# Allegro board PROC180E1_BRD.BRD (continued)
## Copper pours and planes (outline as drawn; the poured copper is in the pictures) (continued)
DGND on TOP: 117.58,45.41 116.52,45.41 116.52,43.52 117.58,43.52
DGND on TOP: 128.6,47.74 129.79,47.74 129.79,49.33 128.6,49.33
DGND on TOP: 53.99,21.67 53.99,17.76 56.74,17.76 56.74,21.67
DGND on TOP: 21.53,36.95 21.53,35.67 22.63,35.67 22.63,36.95
DGND on TOP: 130.52,130.5 130.5,130.52 128.37,130.52 127.78,131.11 127.78,137.09 128.48,137.8 133.89,137.8 134.19,137.51 134.19,130.85 133.84,130.5
DGND on TOP: 129.33,45.57 125.72,45.57 125.72,43.91 128.69,43.91 129.33,44.55
DGND on TOP: 85.16,45.41 84.09,45.41 84.09,43.52 85.16,43.52
DGND on TOP: 116.73,66.74 116.73,65.64 118.02,65.64 118.02,66.74
DGND on TOP: 125.58,45.41 124.52,45.41 124.52,43.52 125.58,43.52
DGND on TOP: 14.65,145.07 14.65,141.22 14.6,141.17 13.11,141.17 12.99,141.3 12.99,145 13.06,145.07
DGND on TOP: 63.89,24.66 63.89,26.79 63.65,27.03 62.17,27.03 62.06,26.93 62.06,22.52 63.07,22.52 63.07,24.25 63.31,24.5 63.73,24.5
DGND on TOP: 13.99,1.02 11.02,3.99 11.02,19.74 15.52,19.74 15.52,11.07 16.32,10.27 16.32,8.75 17.99,7.08 25.49,7.08 25.49,1.02
DGND on TOP: 43.11,57.6 43.24,57.47 43.24,56.31 43.42,56.13 46.29,56.13 46.7,56.54 47.08,56.54 47.48,56.13 50.15,56.13 50.58,56.57 50.58,57.05 51.11,57.58 53.62,57.58 55,56.2 55,55.04 54.87,54.91 54.49,54.91 54.32,55.09 39.74,55.09 39.43,54.79 38.77,54.79 38.62,54.94 38.62,56.54 39.68,57.6
DGND on TOP: 53.83,69.04 54.04,68.83 54.04,67.03 53.73,66.73 50.58,66.73 50.51,66.8 50.51,68.35 50.4,68.45 47.38,68.45 47.05,68.12 46.67,68.12 46.34,68.45 43.52,68.45 43.16,68.1 43.16,66.6 42.99,66.42 39.71,66.42 39.46,66.67 39.46,68.88 39.61,69.04
DGND on TOP: 12.9,157.48 12.9,155.14 14.61,155.14 14.61,157.48
DGND on BOTTOM: 51.81,11.24 51.81,9.41 53.77,9.41 53.77,11.24
DGND on BOTTOM: 84.4,114.79 83.74,114.79 83.67,114.72 83.67,113.24 83.5,113.06 83.5,112.58 83.56,112.52 84.31,112.52 84.53,112.74 84.53,112.74 84.53,114.65
DGND on BOTTOM: 130.31,43.61 131.75,43.61 131.75,47.23 131.58,47.41 130.01,47.41 129.74,47.14 129.74,44.18
DGND on BOTTOM: 48.81,19.31 47.46,19.31 47.22,19.07 47.22,16.83 47.38,16.68 48.75,16.68 49.03,16.96 49.03,19.08
DGND on BOTTOM: 54.1,11.7 54.1,8.87 57.43,8.87 57.43,11.7
DGND on BOTTOM: 31.62,10.24 31.62,12.77 27.95,12.77 27,11.82 27,10.01 27.18,9.83 31.2,9.83
DGND on BOTTOM: 67.48,164.73 69.07,164.73 69.26,164.92 69.26,166.18 68.91,166.54 67.74,166.54 67.48,166.28
DGND on BOTTOM: 66.2,16.08 66.2,12.42 69.75,12.42 69.75,16.08
DGND on BOTTOM: 83.85,158.03 83.85,155.93 84.25,155.53 85.12,155.53 85.48,155.88 85.48,157.43 84.75,158.16 83.99,158.16
DGND on BOTTOM: 27.57,30.82 23.78,30.82 23.78,25.36 27.57,25.36
DGND on BOTTOM: 92.43,35.21 90.26,35.21 90.08,35.03 90.08,34.39 90.2,34.27 91.12,34.27 91.31,34.08 91.31,33.11 91.62,32.81 91.62,31.98 91.68,31.92 92.99,31.92 93.25,32.18 93.25,32.4 92.79,32.86 92.79,33.8 92.43,34.16
DGND on BOTTOM: 44.92,55.89 44.92,51.71 48.92,51.71 48.92,56.1 49.02,56.21 53.7,56.21 53.79,56.3 53.79,57.83 53.69,57.94 44.33,57.94 44.1,58.17 44.1,61.14 44.76,61.8 45.93,61.8 46.29,61.44 46.26,61.42 46.26,60.6 46.37,60.5 47.46,60.5 47.61,60.66 47.61,61.65 47.84,61.87 49.11,61.87 49.31,61.67 49.31,61.47 49.36,61.42 49.84,61.42 50,61.57 50,62.51 49.77,62.74 47.61,62.74 47.48,62.87 47.51,62.89 47.51,63.86 47.3,64.06 46.29,64.06 46.14,63.91 46.14,62.89 45.83,62.59 41.84,62.59 41.64,62.79 41.64,63.55 42.43,64.34 42.43,67.89 41.49,68.83 40.12,68.83 39.71,68.43 39.71,56.42 40.08,56.05 44.76,56.05
DGND on BOTTOM: 93.38,30.45 93.38,27.61 95.02,27.61 95.02,30.45
DGND on BOTTOM: 69.8,114.93 68.5,114.93 68.37,114.8 68.37,114.13 68.47,114.02 69.74,114.02 69.85,114.14 69.85,114.88
DGND on BOTTOM: 82.05,75.1 84.43,75.1 89.05,70.48 89.05,53.33 84.2,48.47 63.79,48.47 61.25,51.01 61.25,69.91 64.79,73.45 68.48,73.45 68.76,73.17 68.76,72.47 64.13,67.84 64.13,51.49 66.01,49.61 69.62,49.61 69.92,49.9 69.92,50.63 70.29,51 84.01,51 85.11,52.11 85.11,69.03 84.05,70.09 84.05,70.82 84.13,70.9 84.13,71.42 83.53,72.03 83.53,72.57 82.2,73.89 82.17,73.89 82.05,74.01
DGND on BOTTOM: 42.96,66.32 53.07,66.32 53.58,66.83 53.58,68.86 53.45,68.99 51.92,68.99 51.79,68.86 41.9,68.86 41.52,69.24 40.44,69.24 40.2,69 40.2,64.81 40.7,64.31 42.3,64.31 42.43,64.44 42.43,65.79
DGND on BOTTOM: 66.55,114.9 65.41,114.9 65.41,114.66 65.41,114.66 65.41,114.1 65.1,113.79 65.1,113.16 65.2,113.06 65.53,113.06 65.91,113.45 65.91,113.75 66.55,114.39
DGND on BOTTOM: 53.43,30.1 53.43,26.46 56.27,26.46 56.27,30.1
DGND on BOTTOM: 53.38,22.97 53.38,18.57 56.86,18.57 56.86,22.97
DGND on L02_GND01: 11.02,4.99 11.02,184.36 13.47,186.82 134.49,186.82 135.98,185.32 135.98,6.56 132.29,6.56 130.45,4.72 130.45,1.02 14.99,1.02 ; 2 cut-outs
DGND on L04_PWR1: 85.11,111.33 85.11,98.21 91.68,91.63 91.68,79.61 91.33,79.27 90.6,79.27 89.86,78.53 89.86,59.49 82.54,52.17 71.02,52.17 70.34,51.49 70.34,41.43 71.08,40.69 73.18,40.69 79.59,34.28 93.41,34.28 95.12,35.99 120.9,35.99 121.78,36.88 121.78,56.74 114.57,63.95 110.66,63.95 105.75,68.87 105.75,95.24 104.2,96.79 104.2,108.88 96.42,116.66 92.2,116.66 89.23,119.64 89.23,123.92 90.75,125.44 93.19,125.44 93.6,125.85 93.6,126.66 93.24,127.02 85.04,127.02 84.35,126.33 84.35,115.67 83.75,115.07 83.75,112.68
DGND on L04_PWR1: 73.28,14.15 134.94,14.15 135.91,13.18 135.91,5.95 131.12,1.16 73.28,1.16
DGND on L05_SIG02: 59.79,70.16 60.58,70.16 61.57,69.17 61.57,59.86 66.53,54.9 82.35,54.9 86.8,59.35 86.8,69.11 81.9,74.01 81.9,76.97 83.06,78.13 86.37,78.13 90.89,73.61 90.89,54.67 85.84,49.62 64.08,49.62 58.04,55.66 58.04,68.41
DGND on L05_SIG02: 73.51,12.63 73.51,1.18 131.27,1.18 135.82,5.74 135.82,18.55 69.97,18.55 67.57,20.96 67.57,25.18 66.56,26.19 64.01,26.19 63.37,25.55 63.37,22.56 61.55,20.75 61.55,13.33 72.81,13.33
DGND on L05_SIG02: 17.93,38.39 20.06,38.39 20.7,37.75 20.7,32.45 22.25,30.9 22.25,20.12 25.72,16.66 25.72,1.92 25.27,1.48 15.05,1.48 11.13,5.41 11.13,23.97 11.29,24.14 14.74,24.14 17.25,26.64 17.25,37.71
DGND on L06_PWR2: 61.58,59.46 66.23,54.81 82.26,54.81 86.49,59.05 86.49,71.03 81.3,76.22 75.98,76.22 74.64,74.87 69.15,74.87 68.44,75.58 67.4,75.58 67.22,75.4 67.22,75.2 66.84,74.81 65.09,74.81 64.38,74.11 64.38,73.77 61.58,70.98
DGND on L07_GND02: 11.02,4.99 11.02,184.36 13.47,186.82 134.49,186.82 135.98,185.32 135.98,6.56 132.29,6.56 130.45,4.72 130.45,1.02 14.99,1.02 ; 7 cut-outs
DVDD3V3 on TOP: 51.57,62.43 52.26,62.43 52.46,62.23 52.46,61.09 52.31,60.93 51.22,60.93 50.94,61.21 50.94,61.47 51.34,61.87 51.34,62.2
VBAT_IN on TOP: 79.48,169.52 79.48,166.92 80.92,165.49 80.92,164.25 81.01,164.16 81.21,163.96 81.21,162.62 81.43,162.62 81.45,162.64 81.45,164.11 81.4,164.15 81.4,164.99 81.54,165.13 81.54,169.41 81.43,169.52
VBUS_5V0_TYPEA on TOP: 60.63,12.42 60.63,11.57 60.87,11.33 62.18,11.33 62.33,11.48 62.33,15.29 62.32,15.29 63.22,16.19 63.22,19.77 62.94,20.04 59.87,20.04 59.87,13.18
VBUS_5V0_TYPEA on BOTTOM: 67.43,20.45 61.13,20.45 60.85,20.17 60.85,17.64 65.2,17.64 65.2,16.98 66.2,16.98 66.2,17.95 67.42,17.95 67.62,18.15 67.62,20.26
VBUS_5V0_TYPEA on BOTTOM: 60.6,15.13 60.6,11.36 64.06,11.36 64.06,15.13
VBUS_TYPEC1 on L05_SIG02 (solid shape): outline of 1023 points within 26.3,4.67 37.85,18.54
VBUS_TYPEC2 on BOTTOM (solid shape): outline of 424 points within 42.91,5.2 58.47,17.56
VBUS_TYPEC2 on L05_SIG02: 41.25,11.08 41.25,22.44 46.35,22.44 48.3,20.48 48.3,17.54 48.97,16.87 58.99,16.87 59.23,16.64 59.23,13.49 58.26,12.53 54.23,12.53 52.15,10.45 52.15,5.34 51.54,4.74 46.84,4.74 46.44,5.14 46.44,8.84 44.19,11.08
VCC1V1 on TOP: 55.01,54.55 47.42,54.55 47.42,51.18 56.82,51.18 56.82,53.54 55.5,53.54 55.01,54.03
VCC1V1 on BOTTOM: 49.54,55.85 49.54,51.66 54.01,51.66 54.01,55.85
VCC1V1_SW on TOP: 50.2,56.46 50.2,57.98 50.03,58.16 48.84,58.16 47.54,59.46 47.54,60.62 47.21,60.62 47.21,56.46
VCC1V8_SYS on TOP: 14.42,105.56 18.4,105.56 18.52,105.45 18.52,104.19 18.44,104.11 16,104.11 15.77,104.34 14.47,104.34 14.41,104.4 14.41,105.55
VCC1V8_SYS on TOP: 132.58,131.95 128.6,131.95 128.48,132.06 128.48,133.32 128.56,133.4 131,133.4 131.23,133.17 132.53,133.17 132.59,133.11 132.59,131.96
VCC1V8_SYS on TOP: 46.14,54.51 46.14,49.89 38.43,49.89 37.63,50.69 37.63,54.17 37.96,54.51
VCC1V8_SYS on TOP: 87.55,152.35 87.55,154.46 85,154.46 85,152.35
VCC1V8_SYS on TOP: 42.91,156.11 42.91,155.17 43.12,154.97 44.43,154.97 44.6,155.14 44.6,155.73 44.23,156.11
VCC1V8_SYS on TOP: 118.38,142.05 118.38,139.95 118.59,139.74 119.36,139.74 119.52,139.9 119.52,141.97 119.44,142.05
VCC1V8_SYS on TOP: 52.56,65.41 52.56,64.74 52.38,64.57 51.42,64.57 50.53,63.68 49.57,63.68 49.5,63.74 49.5,63.96 49.53,63.98 50.2,63.98 50.28,64.06 50.28,64.47 50.91,65.11 50.91,65.43 51.09,65.61 52.36,65.61
VCC1V8_SYS on BOTTOM: 44.18,51.92 44.18,55.48 39.87,55.48 38.61,54.22 37.68,54.22 37.68,50.72 42.99,50.72
VCC1V8_SYS on BOTTOM: 64.16,117.64 64.16,116.53 64.3,116.39 65.07,116.39 65.32,116.64 65.32,117.72 65.25,117.79 64.31,117.79
VCC1V8_SYS on BOTTOM: 104.11,73.73 105.75,73.73 105.77,73.71 105.77,72.57 105.53,72.33 104.31,72.33 104.08,72.56 104.08,73.69
VCC1V8_SYS on BOTTOM: 83.89,110.51 84.72,110.51 84.99,110.78 84.99,111.5 84.74,111.75 83.89,111.75 83.76,111.62 83.76,110.64
VCC1V8_SYS on L03_SIG01: 94,163.07 94,158.76 95.02,157.73 112.41,157.73 115.63,160.94 116.65,160.94 118.17,159.42 131.33,159.42 133.21,161.3 133.21,162.41 132.69,162.92 130.64,162.92 130.12,162.41 116.55,162.41 115.52,163.43 112.7,163.43 112.21,162.95 101.1,162.95 100.59,163.46 94.38,163.46 ; 2 cut-outs
VCC1V8_SYS on L04_PWR1: 52.15,65.8 47.8,65.8 47.29,65.3 45.75,65.3 44.61,64.15 44.61,60.98 43.16,59.54 41.31,59.54 40.35,58.58 31.99,58.58 30.96,57.55 28.01,57.55 25.95,55.49 25.95,42.36 27.1,41.22 29.58,41.22 34.68,46.31 34.68,49.42 35.89,50.63 49.26,50.63 50.2,51.56 50.2,61.99 50.62,62.41 52.34,62.41 52.59,62.66 52.59,65.36
VCC1V8_SYS on L05_SIG02: 59.97,38.71 36.21,38.71 20.42,54.49 20.42,96.99 23.54,100.11 23.54,108.2 25.35,110.01 41.21,110.01 41.56,109.67 41.56,95.18 37.14,90.76 37.14,59.54 40.29,56.38 40.29,51.32 39.7,50.73 39.7,47.22 40.44,46.49 65.34,46.49 67.3,44.53 67.3,29.09 65.79,27.58 64.76,27.58 59.97,32.37
VCC1V8_SYS on L06_PWR2: 11.99,85.48 14.59,82.88 27.37,82.88 32.84,88.34 61.43,88.34 65.28,92.18 92.17,92.18 94.49,89.86 94.49,79.55 91.72,76.78 91.72,67.74 94.11,65.35 94.38,65.35 95.97,63.76 95.97,62.8 97.35,61.42 104.85,61.42 105.07,61.64 105.07,103.95 109.99,108.87 118.31,108.87 118.31,117.82 114.47,121.66 109.86,121.66 109.36,122.16 109.36,126.95 112.43,130.02 133.92,130.02 135.1,131.19 135.1,184.48 132.9,186.68 14.01,186.68 11.99,184.66
VCC1V8_SYS_SW on TOP: 43.52,56.46 43.52,58.16 44.9,58.16 46.21,59.46 46.21,60.62 46.54,60.62 46.54,56.46
VCC1V8_VDD18 on L03_SIG01: 42.95,156.15 42.33,156.76 37.22,156.76 36.19,157.79 36.19,163.64 36.91,164.36 38.99,164.36 39.29,164.66 39.29,171.34 39.83,171.88 43.31,171.88 44.63,173.2 45.83,173.2 47.6,171.43 47.6,156.69 47.06,156.15 ; 1 cut-out
VCC1V8_VDD18 on L05_SIG02: 58.83,108.2 57.3,109.72 43.55,109.72 42.38,108.55 42.38,95.82 44.3,93.9 56.33,93.9 58.83,96.4
VCC1V8_VDD18 on L06_PWR2: 47.16,105.42 49.24,103.34 51.51,103.34 52.87,104.7 52.87,156.75 49.14,160.48 36.22,160.48 35.2,159.46 35.2,157.57 35.88,156.88 44.19,156.88 45.14,155.93 45.82,155.93 47.16,154.6
VCC3V3_TA on TOP: 113.56,68.43 113.05,68.43 112.93,68.31 112.93,66.65 113.07,66.52 113.46,66.52 113.56,66.62
VCC3V3_TA on BOTTOM: 34.61,31.78 34.61,27.6 36.26,27.6 36.26,31.48 35.96,31.78
VCC3V3_TA on L04_PWR1: 34.36,29.65 34.88,29.13 38.4,29.13 41.22,31.95 58.5,31.95 59.58,33.04 69.68,33.04 77.24,25.48 77.24,14.88 134.98,14.88 135.94,15.84 135.94,125.78 134.99,126.74 95.29,126.74 93.68,125.13 90.95,125.13 89.66,123.83 89.66,119.88 92.39,117.15 94.46,117.15 94.5,117.19 96.54,117.19 104.88,108.85 104.88,96.8 106.37,95.3 106.37,69.31 110.66,65.02 114.51,65.02 122.61,56.92 122.61,37.29 121.08,35.75 95.57,35.75 93.71,33.9 79.32,33.9 73.3,39.92 60.29,39.92 58.82,38.44 39.56,38.44 34.36,33.24
VCC3V3_XDS on TOP: 119.37,64.45 118.3,64.45 118.2,64.55 118.2,66.58 118.4,66.77 119.33,66.77 119.37,66.73
VCC3V3_XDS on L06_PWR2: 105.99,101.6 112.96,108.58 119.1,108.58 119.95,109.44 119.95,118.32 115.57,122.7 110.38,122.7 109.87,123.21 109.87,125.86 112.4,128.39 132.11,128.39 135.98,124.52 135.98,65.02 133.16,62.2 107.55,62.2 105.99,63.77
VCC_0V85 on TOP: 52.77,62.87 52.77,64.08 52.61,64.24 51.62,64.24 50.86,63.48 50.86,63.17 51.29,62.74 52.64,62.74
VCC_0V85 on BOTTOM: 51.34,64.29 51.34,62.64 52.54,62.64 52.54,64.29
VCC_1V8_FT4232 on TOP: 39.44,40.98 40.64,40.98 40.8,41.14 40.8,41.42 40.65,41.57 39.49,41.57 39.33,41.41 37.04,41.41 36.32,42.13 36.32,50.87 36.3,50.9 35.76,50.9 35.73,50.87 35.73,50.18 35.89,50.02 35.89,42.58 35.68,42.36 35.01,42.36 34.86,42.51 34.86,44.83 33.8,45.89 29.33,45.89 28.76,46.46 28.76,47.85 28.7,47.9 28.7,49.46 28.67,49.49 28.41,49.49 28.38,49.46 28.38,47.82 28.26,47.7 28.26,46.04 28.98,45.32 33.33,45.32 34.22,44.42 34.22,41.74 32.48,40 30.4,40 28.93,41.47 25.3,41.47 25.03,41.73 23.61,41.73 23.47,41.59 23.47,41.19 23.6,41.06 28.6,41.06 30.13,39.52 32.87,39.52 34.96,41.61 36.17,41.61 36.69,41.09 39.33,41.09
VCC_1V8_IOVDD on TOP: 88.2,154.96 88.2,152.21 90.45,152.21 90.45,154.96
VCC_1V8_IOVDD on L05_SIG02: 82.04,103.99 83.03,103.99 83.49,104.46 85.48,104.46 85.78,104.16 85.78,101.62 82.38,98.23 74.01,98.23 73.68,98.55 73.68,100.07 74.28,100.67 74.28,101.66 74.72,102.1 80.14,102.1
VCC_1V8_IOVDD on L06_PWR2: 66.39,169.25 74.4,161.24 74.4,158.26 73.87,157.74 70.59,157.74 69.39,156.53 69.39,154.08 70.56,152.91 81.41,152.91 83.44,154.95 88,154.95 88.61,154.34 88.61,152.34 87.62,151.35 87.62,146.55 89.43,144.74 92.22,144.74 93.24,145.75 93.24,148.01 93.13,148.13 93.13,160.22 87.48,165.87 79.86,165.87 79.01,166.72 79.01,172.02 73.08,177.96 68.1,177.96 66.39,176.24
VCC_3V3_AVDD on TOP: 77,154.8 79.08,154.8 79.08,153.93 80.71,153.93 80.71,156.28 78.34,156.28 78.34,157.09 79.31,157.09 79.31,157.79 77.76,157.79 77.76,155.98 76.55,155.98 76.55,154.81 77,154.81
VCC_3V3_AVDD on TOP: 74.97,165.87 74.97,163.35 73.73,163.35 73.73,163.85 73.17,163.85 73.17,162.22 72.6,162.22 72.6,163.9 70.19,163.9 70.19,165.85 71.79,165.85 71.79,164.97 73.73,164.97 73.73,165.87
VCC_3V3_AVDD on L04_PWR1: 74.06,166.2 74.06,163.2 75.41,163.2 75.41,166.2
VCC_3V3_FT4232 on TOP: 20.45,37.84 21.6,37.84 21.69,37.93 22.03,37.93 22.1,38.01 22.1,38.55 22.21,38.66 22.56,38.66 22.82,38.4 22.82,37.47 22.69,37.34 20.45,37.34
VCC_3V3_FT4232 on BOTTOM: 28.57,53.76 20.71,53.76 19.15,52.21 19.15,40.78 21.04,38.9 21.04,37.22 21.47,36.78 23,36.78 23.01,36.8 25.62,36.8 26.76,37.94 26.76,39.35 27.86,40.45 28.41,40.45 28.84,40.87 29.8,40.87 29.83,40.9 29.83,41.08 29.73,41.19 22.47,41.19 22.03,41.63 22.03,48.78 23.1,49.85 28.97,49.85 29.34,49.48 29.34,46.17 29.48,46.03 33.51,46.03 35.45,44.08 35.45,37.06 34.48,36.09 34.48,35.74 35.11,35.11 35.98,35.11 36.84,35.97 36.84,41.05 37.94,42.14 39.92,42.14 40.56,42.78 40.56,43.72 40,44.28 38.95,44.28 36.07,47.17 36.07,50.53 33.8,52.8 29.54,52.8
VCC_3V3_FT4232 on L05_SIG02: 23.1,38.87 21.67,38.87 21.16,38.36 21.16,34.31 23.61,31.87 28.86,31.87 29.28,32.29 29.28,32.87 28.86,33.29 24.6,33.29 23.51,34.39 23.51,38.46
VCC_3V3_MAIN on TOP: 42.14,83.04 42.14,85.1 41.89,85.35 40.46,85.35 40.23,85.59 40.23,86.09 40.3,86.16 42.95,86.16 43.24,85.88 43.24,83.37 42.91,83.04
VCC_3V3_MAIN on TOP: 21.17,60.56 21.17,59.31 23.71,59.31 23.99,59.6 23.99,61.02 22.56,61.02 22.1,60.56
VCC_3V3_MAIN on TOP: 44.6,63.54 42.83,63.54 42.83,63.68 41.86,63.68 41.86,63.67 41.5,63.67 41.5,62.36 42.9,62.36 42.9,63.13 44.6,63.13
VCC_3V3_MAIN on TOP: 30.26,31.75 32.69,31.75 32.69,25.51 28.29,25.51 28.29,30.77 29.28,30.77
VCC_3V3_MAIN on TOP: 61.61,57.96 61.61,56.28 61.62,56.27 62.81,56.27 62.9,56.36 62.9,56.94 62.77,57.06 62.21,57.06 62.09,57.19 62.09,57.97 61.62,57.97
VCC_3V3_MAIN on TOP: 44.53,82.58 44.53,85.26 44.63,85.36 45.57,85.36 45.65,85.28 45.65,82.51 46.37,82.51 46.37,82.51 46.63,82.51 46.87,82.27 46.87,80.26 46.67,80.06 44.48,80.06 44.34,80.19 44.34,81.85 44.03,82.17 44.03,82.5 44.11,82.58
VCC_3V3_MAIN on BOTTOM: 45.81,62.95 45.81,64.58 47.89,64.58 47.89,62.96 49.64,62.96 49.64,65.94 43.01,65.94 43.01,64.44 42.2,63.62 41.65,63.62 41.44,63.41 41.44,62.64 41.66,62.41 43.03,62.41 43.57,62.95
VCC_3V3_MAIN on BOTTOM: 44.76,61.61 44.76,58.24 50.05,58.24 50.3,58.49 50.3,59.8 50.73,60.24 50.73,60.95 50.63,61.05 48.92,61.05 48.92,61.63 47.98,61.63 47.98,59.95 45.81,59.95 45.81,61.61
VCC_3V3_MAIN on BOTTOM: 34.1,31.8 27.9,31.8 27.9,25.29 31.25,25.29 31.65,24.9 31.65,24.52 31.91,24.26 33.72,24.26 33.72,24.98 33.86,25.12 34.46,25.12 34.5,25.16 34.5,25.61 34.1,26.01
VCC_3V3_MAIN on L05_SIG02: 51.09,76.4 51.09,72.82 52.43,71.48 55.5,71.48 56.36,72.34 56.36,73.24 56.09,73.51 53.85,73.51 52.49,74.87 52.49,76.41 51.11,76.41
VCC_3V3_MAIN on L06_PWR2: 51.16,30.39 50.88,30.11 39.84,30.11 34.45,24.71 21.63,24.71 17.64,20.73 17.64,16.44 12.1,16.44 12.1,78.04 13.66,79.6 27.37,79.6 33.53,85.76 49.28,85.76 52.38,82.66 52.38,62.39 50.18,60.19 50.18,34.05 51.16,33.07
VCC_3V3_SYS on TOP (solid shape): 41.2,128.2 41.23,128.12 41.2,128.03 40.52,127.51 39.61,128.12 40.52,128.72
VCC_3V3_SYS on TOP: 75.51,165.82 75.51,163.47 76.54,163.47 76.54,165.82
VCC_3V3_SYS on TOP: 48.36,81.38 48.36,87.48 47.34,88.49 46.21,88.49 45.62,87.91 45.62,86.75 44.48,86.75 44.15,87.09 42.75,87.09 42.75,90.76 51.89,90.76 52.32,90.34 52.32,85.23 51.25,84.16 51.25,81.38
VCC_3V3_SYS on TOP: 21.14,165.88 21.14,169.38 20.9,169.62 20.9,170.36 21.06,170.52 21.88,170.52 21.95,170.45 21.95,165.98 21.24,165.98
VCC_3V3_SYS on TOP: 91.67,45.41 90.5,45.41 90.5,43.65 90.88,43.27 91.13,43.27 91.51,42.89 91.51,42 92.1,42 92.1,43.05 91.67,43.48
VCC_3V3_SYS on TOP: 113.24,169.5 111.51,169.5 111.14,169.87 111.14,171.07 111.26,171.19 113.24,171.19
VCC_3V3_SYS on TOP: 124.1,45.41 122.93,45.41 122.93,43.65 123.31,43.27 123.56,43.27 123.94,42.89 123.94,42 124.53,42 124.53,43.05 124.1,43.48
VCC_3V3_SYS on BOTTOM: 101.09,76.49 102.56,76.49 102.56,77.46 101.09,77.46
VCC_3V3_SYS on BOTTOM: 81.54,112.38 82.48,112.38 82.6,112.5 83.27,112.5 83.31,112.54 83.31,114.72 83.24,114.8 82.64,114.8 82.55,114.7 82.55,113.14 82.13,112.72 81.56,112.72 81.54,112.7
VCC_3V3_SYS on BOTTOM: 62.13,111.51 62.13,112.16 61.8,112.49 61.35,112.49 61.35,113.29 61.19,113.45 61.19,114.01 61.86,114.01 61.86,113.1 62.45,112.51 62.45,111.59 62.48,111.56 62.43,111.51
VCC_3V3_SYS on BOTTOM: 91.62,31.14 92.8,31.14 92.8,27.46 91.38,27.46 91.16,27.68 91.16,28.45 91.62,28.91
VCC_3V3_SYS on BOTTOM: 67.54,105.32 67.54,102.24 67.84,101.93 68.34,101.93 68.6,102.2 68.6,102.71 68.21,103.1 68.21,105.19 68,105.4 67.62,105.4
VCC_3V3_SYS on BOTTOM: 73.51,105.26 73.51,106.47 74.31,107.28 75.42,107.28 75.48,107.22 75.48,106.78 75.27,106.57 74.68,106.57 74.07,105.96 74.07,105.32 74.01,105.26
VCC_3V3_SYS on L04_PWR1: outline of 90 points within 11.79,15.16 83.94,126.93
VCC_3V3_SYS on L05_SIG02: 70.64,19.1 67.95,21.79 67.95,34.08 69.34,35.47 69.34,35.91 69.47,35.91 71.62,38.07 78.74,38.07 78.74,33.45 82.91,29.27 113.19,29.27 114.72,30.8 126.05,30.8 127.6,32.35 127.6,41.07 127.01,41.66 125.16,41.66 124.57,41.07 124.57,36.14 122.32,33.89 119.2,33.89 116.86,36.22 116.86,47.09 114.95,49 95.57,49 91.58,52.99 91.58,74.43 85.44,80.57 85.44,91.2 83.13,93.51 60.22,93.51 59.56,94.17 59.56,109.71 58.45,110.82 23.68,110.82 23.68,142.14 22.69,143.13 22.69,151.08 21.93,151.84 11.91,151.84 11.03,152.73 11.03,176.57 135.77,176.57 135.77,19.1 ; 3 cut-outs
VCC_3V3_SYS on L06_PWR2: 75.59,41.74 75.59,33.07 74.32,31.81 65.69,31.81 65.09,31.21 65.09,14.34 65.91,13.52 72.56,13.52 73.71,12.37 73.71,7.76 129.74,7.76 134.18,12.2 134.18,57.85 131.21,60.82 98.01,60.82 97.29,60.1 97.29,49.46 95.92,48.09 81.94,48.09
VCC_5V0 on TOP: 59.72,22.49 59.87,22.34 61.53,22.34 61.75,22.56 61.75,27.96 59.72,27.96
VCC_5V0 on TOP: 18.43,102.96 16.02,102.96 15.74,102.68 13.65,102.68 13.65,100.92 13.72,100.85 18.33,100.85 18.45,100.96 18.45,102.95
VCC_5V0 on TOP: 128.57,134.55 130.98,134.55 131.26,134.83 133.35,134.83 133.35,136.59 133.28,136.66 128.66,136.66 128.55,136.55 128.55,134.56
VCC_5V0 on TOP: 15.15,146.57 15.15,145.52 14.97,145.35 14.97,141.28 15.1,141.15 16.39,141.15 16.71,141.48 16.71,145 16.44,145.28 15.79,145.28 15.46,145.6 15.46,146.57
VCC_5V0 on L04_PWR1: 135.68,146.77 135.44,147.01 135.44,169.83 125.66,179.61 17.22,179.61 11.99,174.38 11.99,101.68 12.88,100.8 26.17,100.8 27.04,101.67 27.04,112.56 38.19,123.72 49.05,123.72 52.87,127.54 134.47,127.54 135.68,128.76
VCC_5V0 on L05_SIG02: 12.2,85.76 11.08,84.64 11.08,40.45 12.31,39.22 23.63,39.22 31.7,31.15 43.94,31.15 44.89,30.2 44.89,23.37 45.33,22.93 47.37,22.93 49.38,20.91 49.38,17.6 49.62,17.36 60.89,17.36 60.89,20.97 62.67,22.75 62.67,29.24 59.48,32.42 59.48,36.22 58.09,37.61 35.07,37.61 19.12,53.56 19.12,97.06 22.79,100.73 22.79,141.72 22.13,142.39 13.01,142.39 12.2,141.57
VCC_CORE on TOP: 40.55,72.76 39.38,71.6 39.38,69.57 39.51,69.44 54.04,69.44 54.04,71.46 52.69,72.8 50.24,72.8 49.99,73.05 49.99,74.08 43.89,74.08 43.89,72.76
VCC_CORE on BOTTOM: 40.2,72.77 40.2,69.52 51.87,69.52 52.1,69.29 53.68,69.29 53.68,72.77
VCC_SDIO on TOP: 15.45,146.93 14.17,146.93 14.03,147.06 14.03,151.09 14.13,151.19 15.42,151.19 15.47,151.14 15.47,149.34 15.32,149.19 15.32,147.91 15.45,147.79
VDD1_LPDDR4_1V8 on BOTTOM: 73.02,75.88 79.78,75.88 83.4,72.26 83.4,70.22 84.55,69.07 84.55,53.12 82.99,51.56 67.33,51.56 66.14,52.75 66.14,68.44 68.32,70.62 68.32,71.18 ; 1 cut-out
VDD_2V5 on TOP: 83.67,45.56 82.5,45.56 82.5,43.84 83.51,42.82 83.51,42 84.1,42 84.1,43.05 83.67,43.48
VDD_2V5 on TOP: 116.1,45.41 114.93,45.41 114.93,43.79 115.1,43.62 115.21,43.62 115.94,42.89 115.94,42 116.53,42 116.53,43.05 116.1,43.48
VDD_2V5 on BOTTOM: 92.86,36.11 92.86,34.15 93.02,34 93.02,32.96 93.2,32.77 96.19,32.77 96.42,33.01 96.42,36.11
VDD_2V5 on L05_SIG02: 95.97,38.53 95.42,37.97 92.67,37.97 91.7,38.94 91.7,44.74 90.94,45.5 82.64,45.5 82.26,45.12 82.26,42.52 83.58,41.21 83.58,38.34 82.03,36.79 82.03,32.99 84.96,30.06 112.98,30.06 112.98,40.74 114.51,42.27 115.73,42.27 116.19,42.73 116.19,46.83 114.58,48.44 97.77,48.44 95.97,46.64
VDD_CANUART on TOP: 44.4,79.47 44.4,78.81 44.67,78.54 47.99,78.54 53.69,72.84 56.55,72.84 57.12,72.27 58.01,72.27 58.17,72.44 58.17,73.19 58.02,73.35 54.28,73.35 48.19,79.43 46.04,79.43 46,79.47
VDD_CANUART on L06_PWR2: 67.32,77.53 65.92,77.53 65.29,76.89 58.77,76.89 58.23,76.35 58.23,75.02 57.44,74.24 57.44,72.89 57.58,72.75 58.05,72.75 58.27,72.97 58.27,74.09 60.46,76.28 65.47,76.28 66.25,77.06 67.32,77.06
VDD_CORE on TOP: 91.5,75.99 90.3,75.99 90.3,80.36 90.54,80.59 90.54,81.31 91.5,81.31
VDD_CORE on TOP: 43.81,75.87 43.81,74.53 50.18,74.53 50.18,76.13 47.96,78.35 42.06,78.35 42.06,75.87
VDD_CORE on L04_PWR1: 58.17,99.44 82.44,99.44 91.5,90.37 91.5,80.16 91.03,79.69 84.32,79.69 83.3,78.68 80.38,78.68 79.07,77.36 73.54,77.36 73.25,77.07 65.41,77.07 61.24,72.91 41.29,72.91 39.5,74.7 39.5,82.87 44.36,87.73 48.16,87.73 53.46,93.04 53.46,94.73
VDD_CORE_0V85 on BOTTOM: 54.13,66.29 54.7,65.71 54.7,64.51 53.87,63.68 53.29,63.68 53.29,62.59 53.92,62.59 56.1,64.77 56.1,66.04 55.2,66.94 55.2,70.42 55.45,70.67 58.16,70.67 58.29,70.79 58.29,71.97 58.07,72.19 54.32,72.19 54.13,72
VDD_CORE_REG_SW1 on TOP: 44.74,66.26 46.21,64.79 46.21,64.05 46.54,64.05 46.54,67.87 46.34,68.07 43.61,68.07 43.54,68 43.54,66.26
VDD_CORE_REG_SW2 on TOP: 49.01,66.26 47.54,64.79 47.54,64.05 47.21,64.05 47.21,67.9 47.38,68.07 50.2,68.07 50.2,66.26
VDD_LPDDR4 on TOP: 57.46,51.17 57.46,55.16 62.05,55.16 62.98,56.08 62.98,71.16 64.15,72.33 66.77,72.33 68.54,70.55 82.41,70.55 84.19,72.33 86.83,72.33 88.08,71.08 88.08,67.35 86.96,66.24 86.96,54.21 84.96,52.21 66.7,52.21 63.63,49.14 59,49.14 58.79,49.34 58.79,51.01 58.67,51.13 57.5,51.13 ; 9 cut-outs
VDD_LPDDR4 on L04_PWR1: 65.16,53.09 81.54,53.09 88.09,59.64 88.09,71.73 82.92,76.91 69.57,76.91 69.13,76.46 66.76,76.46 61.51,71.21 61.51,56.74
VDD_MMC1 on TOP: 21.87,164.29 20.4,164.29 20.34,164.23 20.34,160.69 21.89,160.69 21.89,164.27
VDD_MMC1_SD on TOP: 22.24,160.35 16.75,160.35 14.94,158.55 14.94,155.1 16.35,155.1 16.35,158.01 17.88,159.53 22.24,159.53
VDD_MMC1_SD on BOTTOM: 14,156.06 13.93,155.99 13.93,155.21 13.99,155.15 16.23,155.15 16.23,156.06
VDDA1V8 on TOP: 49.19,59.59 49.19,60.48 51.24,60.48 51.39,60.63 52.16,60.63 52.54,60.25 52.54,58.9 52.6,58.84 54.33,58.84 54.68,59.18 54.68,60.09 54.83,60.25 55.95,60.25 56.02,60.19 56.02,57.56 55.97,57.52 54.7,57.52 54.33,57.89 52.48,57.89 50.78,59.59
VDDA_1V8 on TOP: 89.44,81.67 89.19,81.92 89.19,86.51 92.43,86.51 92.43,82.23 91.86,81.67
VDDA_1V8 on TOP: 59.17,71.92 59.41,72.16 60.12,72.16 60.27,72.02 60.27,66.11 58.95,64.79 58.95,58.24 58.23,57.52 56.37,57.52 56.33,57.56 56.33,60.13 56.5,60.3 57.85,60.3 57.97,60.42 57.97,65.21 59.17,66.41
VDDA_1V8 on BOTTOM: 89.9,80.01 89.9,78.64 93.13,78.64 93.13,80.01
VDDA_1V8 on L05_SIG02: 74.51,78.44 74.51,77.89 79.76,77.89 79.76,78.51 79.39,78.88 74.95,78.88
VDDA_1V8 on L06_PWR2: 87.36,58.76 87.36,71.18 81.74,76.8 79,76.8 78.4,77.41 78.4,78.55 78.66,78.81 79.75,78.81 79.84,78.9 79.84,81.47 76.46,84.85 72.02,84.85 71.05,85.82 71.05,88.7 71.56,89.21 91.57,89.21 93.29,87.49 93.29,78.99 91.02,76.72 91.02,67.48 95.4,63.1 95.4,50.37 93.57,48.54 80.52,48.54 74.41,42.43 74.41,33.92 73.64,33.14 53.91,33.14 51.46,35.59 51.46,55.16 52.93,56.63 56.11,56.63 56.65,57.17 56.65,58.14 57.97,59.46 60.94,59.46 66.56,53.85 82.46,53.85
VDDA_1V8_FB1 on BOTTOM: 89.57,80.9 87.79,80.9 87.79,78.99 89.57,78.99
VDDA_1V8_FB1 on L03_SIG01: 76.01,82.03 80.5,82.03 80.74,82.27 86.73,82.27 88.1,80.9 89.19,80.9 89.52,80.57 89.52,79.27 89.42,79.17 86.66,79.17 86.22,79.6 82.74,79.6 82.53,79.4 82.53,77.31 82.33,77.1 72.95,77.1 72.71,77.34 72.71,78.59 72.71,78.59 72.71,79.52 73.11,79.92 74.43,79.92 75.95,81.44 76.01,81.5
VDDA_1V8_FB1 on L06_PWR2: 73.83,81.74 74.23,82.15 75.91,82.15 76.21,81.84 76.46,81.84 76.58,81.72 76.58,81.46 76.24,81.12 74.33,81.12 74.09,81.36 73.94,81.36 73.83,81.47
VDDA_1V8_FB2 on TOP: 86.57,81.36 90.23,81.36 90.23,80.64 87.74,80.64 87.46,80.37 86.73,80.37 86.57,80.52
VDDA_1V8_FB_OSC on TOP: 59.53,74.03 59.53,72.38 60.25,72.38 60.25,74.03
VDDA_1V8_FB_OSC on L06_PWR2: 66.37,76.75 65.31,75.69 60.67,75.69 59.21,74.23 59.21,73.19 59.61,72.79 60.22,72.79 60.24,72.81 64.62,72.81 67.28,75.47 73.42,75.47 73.69,75.74 73.69,76.83 73.38,77.14 72.89,77.14 72.5,76.75
VDDA_CORE_CSI on TOP: 86.57,79.89 86.57,78.89 89.76,78.89 89.76,79.89
VDDA_CORE_USB on TOP: 88.07,78.23 88.07,77.11 89.8,77.11 89.8,78.23
VDDA_CORE_USB on BOTTOM: 88.07,78.5 88.07,77.43 89.01,77.43 89.01,78.5
VDDA_CORE_USB on L04_PWR1: 84.36,79.04 88.61,79.04 88.61,76.52 83.95,76.52 83.76,76.71 83.76,78.44
VDDA_DDR_PLL0 on BOTTOM: 59.95,78.64 59.95,77.5 58.43,77.5 58.43,78.64
VDDA_DDR_PLL0 on L06_PWR2: 65.62,78.71 67.47,78.71 67.69,78.93 75.17,78.93 76.18,77.92 76.52,77.92 76.66,77.78 76.66,77.38 76.55,77.26 73.76,77.26 73.15,77.88 65.85,77.88 65.25,77.28 59.72,77.28 59.37,77.63 59.37,78.22 59.7,78.55 60.88,78.55 61.37,78.06 64.96,78.06
VDDA_LM5141 on BOTTOM: 18.98,25.81 18.98,24.5 19.05,24.43 19.05,23.55 18.27,23.55 18.27,25.17 17.81,25.17 17.71,25.28 17.71,25.67 17.85,25.81
VDDA_LM5141 on L04_PWR1: 21.06,20.54 21.06,25.99 20.67,26.38 16.97,26.38 16.46,25.87 16.46,20.58 16.97,20.07 20.59,20.07
VDDR_CORE on BOTTOM: 55.51,70.35 55.51,68.14 58.33,68.14 58.33,70.35
VDDR_CORE on L06_PWR2: 78.2,79.43 78.2,77.2 78.06,77.06 76.79,77.06 76.64,77.22 76.64,77.67 75.98,78.33 75.98,78.54 74.97,79.55 68.03,79.55 67.64,79.16 66.33,79.16 66.17,79.32 65.57,79.32 65.26,79.01 65.26,79.01 64.53,78.28 62.19,78.28 61.45,79.02 59.78,79.02 58.87,78.12 58.87,77.69 56.8,75.62 56.8,71.72 58.4,70.13 58.4,67.83 58,67.43 53.44,67.43 52.83,68.04 52.83,80.21 54.88,82.26 61.08,82.26 61.26,82.08 72.52,82.08 72.98,82.54 72.98,84.36 72.97,84.37 73.2,84.61 73.2,84.62 76.07,84.62 78.2,82.49 78.34,82.49 79.22,81.61 79.22,80.44
VDDSHV_SDIO on TOP: 16.11,149.73 16.25,149.59 20.76,149.59 21.14,149.98 21.14,153.28 20.82,153.61 20.51,153.61 20.14,153.97 20.14,154.82 20.11,154.86 19.87,154.86 19.8,154.79 19.8,153.71 19.65,153.56 19.65,152.39 19.44,152.19 16.26,152.19 16.11,152.04
VDDSHV_SDIO on L05_SIG02: 11.02,87.62 11.02,147.77 14.16,150.91 21.6,150.91 21.81,150.7 21.81,149.62 21.58,149.39 15.26,149.39 11.69,145.82 11.69,88.43 11.77,88.35 11.77,87.65 11.59,87.47 11.17,87.47
(no net) on TOP: 35.74,8.31 35.74,7.43 35.66,7.35 35.37,7.35 35.25,7.24 35.25,6.92 35.35,6.83 35.5,6.83 35.5,5.91 35.79,5.91 35.79,6.83 36.06,6.83 36.17,6.93 36.17,7.23 36.05,7.34 36.05,8.31
(no net) on TOP: 35.8,14.48 35.8,16.36 37.62,16.36 37.62,15.54 37.1,15.03 37.1,14.48
(no net) on TOP: 50.94,24.98 51.65,24.98 52.87,26.2 52.87,29.99 49.1,29.99 48.88,29.77 48.88,26.75 49.13,26.49 50.58,26.49 50.94,26.14
(no net) on TOP: 50.74,8.31 50.74,7.43 50.66,7.35 50.37,7.35 50.25,7.24 50.25,6.92 50.35,6.83 50.5,6.83 50.5,5.91 50.79,5.91 50.79,6.83 51.06,6.83 51.17,6.93 51.17,7.23 51.05,7.34 51.05,8.31
(no net) on TOP: 50.86,24.15 56.69,24.15 56.69,26.04 53.25,26.04 52,24.8 50.86,24.8
(no net) on TOP: 32.99,5.87 32.99,6.75 32.91,6.83 32.62,6.83 32.5,6.94 32.5,7.26 32.6,7.35 32.75,7.35 32.75,8.27 33.04,8.27 33.04,7.35 33.31,7.35 33.42,7.25 33.42,6.95 33.3,6.84 33.3,5.87
(no net) on TOP: 50.06,19.85 50.06,20.93 50.96,21.82 50.96,22.85 51.89,22.85 53.71,21.03 53.71,17.47 53.98,17.2 55.96,17.2 55.96,16.25 49.44,16.25 49.08,16.6 49.08,19.72 49.21,19.85
(no net) on TOP: 47.99,5.87 47.99,6.77 47.93,6.83 47.53,6.83 47.38,6.97 47.38,7.21 47.53,7.35 47.75,7.35 47.75,8.27 48.04,8.27 48.04,7.35 48.18,7.35 48.3,7.23 48.3,5.87
(no net) on TOP: 41.32,13.64 41.32,16.19 41.46,16.33 42.1,16.33 42.23,16.2 42.23,13.64
(no net) on TOP: 42.54,14.01 42.54,16.25 42.67,16.38 44.7,16.38 44.83,16.26 44.83,15.7 45.24,15.28 45.24,14.01
(no net) on TOP: 53.36,21.95 56.7,21.95 56.7,23.75 50.86,23.75 50.86,23.12 52.18,23.12
(no net) on TOP: 11.02,4.99 11.02,181.65 16.19,186.82 134.49,186.82 135.98,185.32 135.98,6.56 132.29,6.56 130.45,4.72 130.45,1.02 14.99,1.02 ; 200 cut-outs
(no net) on BOTTOM: 35.03,16.26 35.85,16.26 36.18,16.59 36.42,16.59 36.79,16.96 36.79,17.36 37.98,17.36 37.98,16.56 37.67,16.25 37.67,14.57 36.94,14.57 36.62,14.25 35.17,14.25 35.03,14.39
(no net) on BOTTOM: 45.15,9.02 46.04,8.14 46.04,5.2 51.07,5.2 51.56,5.69 51.56,11.28 52.39,12.11 57.12,12.11 58.47,13.46 58.47,17.56 55.88,17.56 55.75,17.43 55.75,15.49 55.63,15.38 54.3,15.38 53.99,15.07 53.99,14.32 53.38,13.7 47.85,13.7 47.34,14.21 45.96,14.21 45.09,15.09 42.91,15.09 42.91,14.07 43.69,14.07 44.64,13.13 44.64,11.48 45.15,10.96
(no net) on BOTTOM: 44.26,17.04 44.26,17.62 43.93,17.95 42.89,17.95 42.89,19.17 42.93,19.22 43.77,19.22 43.77,19.5 40.25,19.5 40.25,17.77 40.4,17.62 42.98,17.62 43.08,17.51 43.42,17.51 43.5,17.44 43.5,17.14 43.68,16.96 44.18,16.96
(no net) on BOTTOM: 41.97,16.46 41.97,17.39 41.31,17.39 41.31,16.56 41.26,16.51 41.26,14.47 41.66,14.06 44.13,14.06 44.13,15.08 42.55,15.08 42.25,15.38 42.25,16.18
(no net) on BOTTOM: 35.82,16.96 35.82,17.62 36.1,17.9 37.07,17.9 37.19,18.02 37.19,19.22 36.35,19.22 36.35,19.5 39.83,19.5 39.83,17.77 39.68,17.62 37.27,17.62 37.17,17.51 36.66,17.51 36.58,17.44 36.58,16.96
(no net) on BOTTOM: 52.72,18.8 52.2,18.8 52.2,16.72 49.41,16.72 49.41,21.26 50.88,21.26 50.88,22.4 52.72,22.4
(no net) on BOTTOM: 32.6,5.11 32.6,9.04 33.3,9.04 33.3,8.56 35.64,8.56 35.64,8.94 36.32,8.94 36.32,5.11
(no net) on BOTTOM: 11.02,4.99 11.02,184.36 13.47,186.82 134.49,186.82 135.98,185.32 135.98,6.56 132.29,6.56 130.45,4.72 130.45,1.02 14.99,1.02 ; 270 cut-outs
(no net) on BOTTOM: 49.39,26.67 52.72,26.67 52.72,29.39 49.39,29.39
(no net) on BOTTOM: 42.13,16.59 42.13,17.41 42.82,17.41 43.6,16.64 44.41,16.64 44.59,16.46 44.59,15.57 44.41,15.39 42.68,15.39 42.53,15.54 42.53,16.19
(no net) on L03_SIG01: 11.02,4.99 11.02,184.36 13.47,186.82 134.49,186.82 135.98,185.32 135.98,6.56 132.29,6.56 130.45,4.72 130.45,1.02 14.99,1.02 ; 268 cut-outs
(no net) on L05_SIG02: 32.15,18.54 33.84,16.86 37.26,16.86 37.85,16.27 37.85,12.92 37.06,12.12 37.06,4.67 31.35,4.67 31.35,8.08 30.05,9.38 27.32,9.38 26.3,10.4 26.3,18.26 26.59,18.54
CLOCK_GENERATOR_SUPPLY on TOP: 75.28,145.19 75.9,145.19 77.15,146.44 77.15,146.64 77.4,146.9 78.46,146.9 78.46,146.89 78.46,144.67 78.34,144.55 77.37,144.55 77.18,144.74 75.27,144.74 75.27,145.18
CLOCK_GENERATOR_SUPPLY on L04_PWR1: 76.69,148.81 71.02,148.81 69.91,147.7 69.91,144.42 70.37,143.96 76.74,143.96 77.82,145.04 77.82,147.67
CPLD1_1V8_BANK_SUPPLY on TOP: 83.57,110.04 84.54,110.04 84.73,110.22 85.05,110.22 85.22,110.05 85.22,109.32 84.98,109.07 83.83,109.07 83.57,109.34
CPLD1_1V8_BANK_SUPPLY on BOTTOM: 80.99,106.74 80.99,104.55 81.34,104.19 81.66,104.19 81.91,104.44 81.91,105.56 81.43,106.04 81.43,106.75 80.99,106.75
CPLD1_1V8_BANK_SUPPLY on BOTTOM: 75.37,109.84 73.24,109.84 73.18,109.78 73.18,108.83 73.26,108.75 73.71,108.75 73.83,108.87 73.83,109.23 73.99,109.39 74.38,109.39 74.52,109.25 75.31,109.25 75.38,109.32 75.38,109.83
CPLD1_1V8_BANK_SUPPLY on BOTTOM: 81.55,110.21 82.67,110.21 82.74,110.28 85.07,110.28 85.21,110.15 85.21,109.2 85.05,109.05 84.34,109.05 83.5,109.88 82.25,109.88 82.25,109.88 81.56,109.88 81.55,109.89
CPLD1_1V8_BANK_SUPPLY on L05_SIG02: 72.49,110.32 85.25,110.32 85.38,110.19 85.38,109.49 84.8,108.91 84.8,106.93 83.22,105.35 82.48,105.35 82.28,105.15 82.28,104.73 80.55,103 72.32,103 71.84,103.48 71.84,106.87 71.36,107.35 71.36,108.47 72.09,109.21 72.09,109.92
CPLD1_TCK on BOTTOM (solid shape): 111.96,149.81 112.04,149.79 112.06,149.71 111.93,148.67 111.02,148.77 110.91,149.68
CPLD2_1V8_BANK_SUPPLY on BOTTOM: 64.62,111.5 64.62,113.11 63.93,113.79 63.93,116.19 65.14,116.19 65.14,114.26 64.92,114.05 64.92,112.42 64.98,112.36 64.98,111.49 64.62,111.49
CPLD2_1V8_BANK_SUPPLY on BOTTOM: 68.14,111.33 68.93,111.33 69.09,111.49 69.09,112.4 68.9,112.59 68.5,112.59 68.35,112.74 68.35,113.6 68.47,113.71 69.67,113.71 69.78,113.61 69.78,111.04 69.67,110.94 68.18,110.94 68.14,110.98
CPLD2_1V8_BANK_SUPPLY on L06_PWR2: 69.66,115.48 64.03,115.48 63.5,114.95 63.5,105.15 64.99,103.67 69.15,103.67 70.54,105.06 70.54,114.59
DIX_RX1 on TOP (solid shape): 37.86,178.96 37.01,177.82 36.93,177.78 36.86,177.82 35.98,178.96 36.92,179.7
DIX_TX on TOP (solid shape): 53.86,178.96 52.97,177.8 52.9,177.77 52.82,177.81 51.98,178.96 52.92,179.7
DRAIN1 on BOTTOM (solid shape): 39.78,19.5 39.82,19.48 39.83,19.44 39.83,17.79 39.83,17.77 39.82,17.75 39.7,17.63 39.68,17.62 39.66,17.62 39,17.62 39,17.63 38.31,17.63 38.28,17.66 38.28,17.67 36.53,17.67 36.5,17.65 36.48,17.62 36.48,17.11 36.48,17.09 36.47,17.07 36.36,16.97 36.35,16.96 36.33,16.96 35.87,16.96 35.84,16.97 35.82,17.01 35.82,17.59 35.82,17.61 35.84,17.63 36.07,17.87 36.09,17.88 36.11,17.88 36.7,17.88 36.76,17.89 37.2,17.89 37.24,17.9 37.25,17.94 37.25,19.22 37.24,19.26 37.2,19.27 36.41,19.27 36.37,19.29 36.35,19.32 36.35,19.44 36.37,19.47 36.41,19.49 36.62,19.49 36.66,19.48 36.7,19.47 37.47,19.47 37.49,19.48 37.51,19.5
DRAIN1 on TOP: 37.33,19.41 37.33,17.43 39.84,17.43 39.84,19.41
DRAIN2 on BOTTOM (solid shape): 42.58,19.5 42.6,19.49 42.62,19.47 43.4,19.47 43.44,19.48 43.49,19.49 43.72,19.49 43.76,19.47 43.77,19.44 43.77,19.32 43.76,19.29 43.72,19.27 42.91,19.27 42.87,19.26 42.86,19.22 42.86,17.94 42.87,17.9 42.91,17.89 43.92,17.89 43.95,17.92 43.95,17.93 44.25,17.63 44.26,17.61 44.26,17.59 44.26,17.06 44.26,17.04 44.25,17.02 44.2,16.97 44.18,16.96 44.16,16.96 43.73,16.96 43.71,16.96 43.69,16.97 43.51,17.15 43.5,17.17 43.5,17.19 43.5,17.42 43.5,17.44 43.48,17.45 43.44,17.5 43.42,17.51 43.4,17.51 43.17,17.51 43.15,17.52 43.14,17.53 42.96,17.7 42.94,17.72 42.92,17.72 41.85,17.72 41.82,17.7 41.8,17.69 41.06,17.69 41.02,17.68 41.01,17.64 40.98,17.62 40.42,17.62 40.4,17.62 40.39,17.63 40.26,17.75 40.25,17.77 40.25,17.79 40.25,19.44 40.26,19.48 40.3,19.5
DRAIN2 on TOP: 40.25,19.41 40.25,17.43 43.07,17.43 43.07,19.41
EEPROM_WP on BOTTOM (solid shape): 58.35,40.65 57.44,40.09 56.8,40.58 56.77,40.65 56.8,40.72 57.44,41.21
FT4232_USB_VBUS on TOP: 14.97,32.18 16.96,32.18 17.89,33.12 18.46,33.12 18.46,36.96 18.97,37.47 18.97,37.81 18.94,37.84 18.24,37.84 18.24,38.55 18.33,38.64 18.94,38.64 19.03,38.74 19.03,39.21 18.9,39.35 17.42,39.35 17.3,39.23 17.3,34.28 16.72,33.69 15.7,33.69 14.97,32.96
LDO_3V3 on L05_SIG02: 43.48,30.52 44.16,29.84 44.16,26.29 42.7,24.83 41.63,24.83 40.23,23.43 40.23,15.83 39.19,15.83 37.82,17.21 34.88,17.21 32.97,19.11 23.93,19.11 22.83,20.21 22.83,28.17 25.17,30.52
MCAN0_CAN_H on TOP (solid shape): 35.14,145.37 35.2,145.35 35.21,145.3 34.89,143.24 33.97,144.13 33.08,145.04
MCAN0_CAN_L on TOP (solid shape): 35.02,148.25 35,148.2 34.95,148.18 33.87,148.32 33.97,149.23 34.88,149.34
MCAN1_CAN_H on TOP (solid shape): 31.12,91.08 31.17,91.07 31.19,91.01 30.87,88.95 29.95,89.85 29.06,90.76
MCAN1_CAN_L on TOP (solid shape): 31,93.97 30.98,93.92 30.93,93.9 29.85,94.04 29.95,94.95 30.86,95.05
MIC1_BIAS on BOTTOM: 83.63,157.82 83.63,155.82 83.54,155.74 82.12,155.74 81.89,155.96 81.89,157.32 82.49,157.93 83.52,157.93
MIC1_BIAS on L03_SIG01: 81.72,156.2 83.13,156.2 85.17,158.24 85.17,158.84 91.49,165.16 91.49,181.63 86.67,181.63 85.05,180.01 85.05,176.61 80.38,171.94 80.38,163.8 80.35,163.77 80.35,157.58
MIC2_BIAS on BOTTOM: 67.38,164.21 69.19,164.21 69.32,164.08 69.32,162.85 68.74,162.27 67.71,162.27 67.35,162.63 67.35,164.18
MIC2_BIAS on L03_SIG01: 68.58,162.02 69.14,162.58 69.14,166.2 72.91,169.97 72.91,173 72.77,173.14 74.35,174.72 74.35,181.08 73.49,181.94 66.65,181.94 66.24,182.34 62.63,182.34 58.57,178.28 58.57,169.91 65.72,162.76 65.72,162.15 65.84,162.02
PCM1_BSTOUT on TOP: 83.28,154.66 83.28,156.54 82.67,156.54 82.67,156.96 81.8,156.96 81.74,156.9 81.74,156.84 81.72,156.83 82.65,155.9 82.65,155.59 82.7,155.54 82.7,154.67 83.27,154.67
PCM2_BSTOUT on TOP: 67.65,165.02 67.65,163.57 68.05,163.18 68.67,163.18 68.69,163.2 68.69,163.44 68.24,163.89 68.24,164.97 68.12,165.09 67.73,165.09
PMIC_LPM_SEL on TOP (solid shape): 29.29,58.34 28.38,57.72 27.66,58.27 27.63,58.34 27.66,58.41 28.38,58.96
SOC_DVDD1V8 on TOP: 68.8,51.25 67.37,51.25 67.24,51.39 66.34,51.39 65.96,51 65.96,50.31 63.14,47.49 46.72,47.49 46.11,48.1 46.11,49.52 40.42,49.52 40.42,48.08 40.88,47.62 41.85,47.62 44.56,44.9 64.16,44.9 69.25,49.98 69.25,50.81
SOC_DVDD1V8 on BOTTOM: 66.28,49.91 66.28,51.2 69.58,51.2 69.58,49.87 66.32,49.87
SOC_DVDD1V8 on L05_SIG02: 75.38,82.64 74.67,81.94 70.87,81.94 70.69,81.76 69.63,81.76 69.12,82.27 69.12,82.37 68.39,83.11 52.08,83.11 50.04,81.06 50.04,73.08 52.01,71.11 55.36,71.11 56.78,72.53 56.78,75.2 58.54,76.96 63.23,76.96 63.54,77.27 80.84,77.27 80.84,75.54 64.7,75.54 57.42,68.26 57.42,47.41 40.44,47.41 40.44,50.77 41.26,51.6 41.26,56.47 37.85,59.88 37.85,85.78 37.87,85.79 37.87,91.04 39.57,92.74 82.69,92.74 83.91,91.52 83.91,83.53 83.03,82.64
SOC_DVDD3V3 on TOP: 52.59,81.05 52.87,80.77 52.87,80.04 52.61,79.78 51.39,79.78 51.14,79.53 51.14,79.15 51.47,78.82 52.82,78.82 52.89,78.74 52.89,77.5 52.59,77.19 50.75,77.19 48.43,79.51 48.43,81.05
SOC_DVDD3V3 on L05_SIG02: 81.17,78.05 80.34,78.05 80.2,78.2 80.2,78.71 79.46,79.46 74.72,79.46 74.46,79.2 74.46,78.99 73.24,77.77 63.26,77.77 62.95,77.47 54.7,77.47 54.32,77.09 51.41,77.09 50.92,77.58 50.92,81.11 52.36,82.55 68.31,82.55 68.91,81.95 68.91,81.52 69.16,81.27 69.47,81.27 70.16,80.57 71.09,80.57 71.95,81.43 74.64,81.43 75.41,82.2 84.28,82.2 84.87,81.62 84.87,79.58 84.05,78.77 81.89,78.77
SOC_VDDSHV5_SDIO on L06_PWR2: 54.35,87.68 53.99,87.31 53.99,84 55.25,82.74 59.58,82.74 59.6,82.72 72.35,82.72 72.58,82.94 72.58,83.68 70.54,85.72 70.54,87.59 70.44,87.68
SW_2V5 on BOTTOM: 93.09,31.65 91.62,31.65 91.62,31.44 92.94,31.44 93.62,30.77 96.06,30.77 96.24,30.95 96.24,32.38 96.23,32.39 93.83,32.39
SW_LM5141 on BOTTOM: 22.65,21.07 22.43,20.84 22.43,20.03 22.69,19.76 22.69,18.55 23.45,17.79 23.45,15.33 23.29,15.17 22.13,15.17 21.55,14.59 21.55,12.49 22.65,12.49 22.93,12.2 22.93,9.87 23.14,9.66 26.7,9.66 26.7,12.37 27.48,13.15 27.48,21.07 25.04,21.07 25.04,22.2 23.56,22.2 23.56,21.07
SW_LM5141 on L04_PWR1: 27.64,17.5 27.64,19.35 27.05,19.94 26.31,19.94 25.99,20.26 25.99,20.76 25.71,21.04 22.47,21.04 21.97,20.55 21.97,19.33 21.6,18.97 11.61,18.97 11.11,18.47 11.11,6.25 15.89,1.48 24.71,1.48 25.54,2.31 25.54,8.33 26.45,9.24 28.92,9.24 29.99,10.31 29.99,15.15
TEST_GPIO3 on TOP (solid shape): 95.24,137.52 94.39,136.9 93.67,137.45 93.64,137.52 93.67,137.59 94.39,138.14
TEST_GPIO3 on BOTTOM (solid shape): 95.24,137.52 94.39,136.9 93.67,137.45 93.64,137.52 93.67,137.59 94.39,138.14
UART_SHIELD on TOP, L02_GND01, L03_SIG01, L04_PWR1, L05_SIG02, L06_PWR2, L07_GND02: 13.78,24.66 11.36,24.66 11.02,25.01 11.02,35.39 11.21,35.58 16.35,35.58 16.76,35.17 16.76,34.46 16.37,34.08 14.99,34.08 14.89,34.17 13.96,34.17 13.58,33.79 13.58,28.41 14.08,27.92 14.66,27.92 14.82,28.08 16.34,28.08 16.71,27.72 16.71,27 15.64,25.93 14.59,25.93 14.16,25.51 14.16,25.05
UART_SHIELD on BOTTOM: 14.59,25.93 14.16,25.51 14.16,25.05 13.78,24.66 11.36,24.66 11.02,25.01 11.02,35.39 11.21,35.58 16.35,35.58 16.76,35.17 16.76,34.46 16.37,34.08 14.99,34.08 14.89,34.17 13.96,34.17 13.58,33.79 13.58,28.41 14.08,27.92 14.66,27.92 14.82,28.08 16.34,28.08 16.71,27.72 16.71,27 15.64,25.93
USB_TYPEA_EARTH on TOP, L02_GND01, L03_SIG01, L04_PWR1, L05_SIG02, L06_PWR2, L07_GND02: 72.4,12.38 70.05,12.38 70.05,8.19 69.25,7.39 60.76,7.39 60.01,8.14 60.01,12.38 57.73,12.38 57.73,1.02 72.4,1.02
USB_TYPEA_EARTH on BOTTOM: 72.4,12.38 70.05,12.38 70.05,8.19 69.25,7.39 60.76,7.39 60.01,8.14 60.01,12.38 58.19,12.38 57.73,11.92 57.73,1.02 72.4,1.02
USB_TYPEC1_EARTH on TOP, BOTTOM, L02_GND01, L03_SIG01, L04_PWR1, L05_SIG02, L06_PWR2, L07_GND02: 40.23,1.02 27,1.02 27,8.23 30.29,8.23 30.55,7.98 30.55,4.27 31.06,3.77 37.76,3.77 38.21,4.23 38.21,7.94 38.51,8.23 40.23,8.23
USB_TYPEC2_EARTH on TOP, BOTTOM, L04_PWR1, L06_PWR2: 55.23,1.02 42,1.02 42,8.23 45.29,8.23 45.55,7.98 45.55,4.27 46.06,3.77 52.76,3.77 53.21,4.23 53.21,7.94 53.51,8.23 55.23,8.23
USB_TYPEC2_EARTH on L02_GND01, L03_SIG01, L05_SIG02, L07_GND02: 55.23,1.02 42,1.02 42,8.23 45.29,8.23 45.55,7.98 45.55,4.27 46.06,3.77 52.76,3.77 53.21,4.23 53.21,7.94 53.51,8.23 55.23,8.23
VMAIN on TOP: 26.28,11.05 27.55,11.05 29.31,12.81 29.31,19.62 29.7,20.01 29.7,20.69 29.67,20.72 26.4,20.72 26.4,22.04 23.83,22.04 23.83,23.54 16.78,23.54 16.78,10.21 18.9,8.09 24.6,8.09 25.7,9.19 25.7,10.47
VMAIN on BOTTOM: 13.94,17.43 12.99,18.39 12.99,23.35 13.24,23.59 14.17,23.59 14.44,23.87 14.44,24.61 14.17,24.88 11.97,24.88 11.62,24.54 11.62,16.22 11.73,16.12 15.14,16.12 16.46,14.79 16.46,9.71 17.07,9.11 20.77,9.11 21.1,9.44 21.1,14.97 22.03,15.9 22.03,17.07 21.77,17.33 20.63,17.33 20.63,19.04 20.16,19.04 20.16,20.36 19.61,20.36 19.61,17.93 18.96,17.93 18.96,17.33 18.51,16.89 16.85,16.89 16.3,17.43
VMAIN on L06_PWR2: 54.37,28.93 53.98,29.32 39.67,29.32 33.31,22.96 21.65,22.96 18.57,19.88 18.57,16.41 17.32,15.16 17.32,11.44 19.41,9.36 57.23,9.36 57.23,12.64 57.46,12.87 60.26,12.87 60.47,12.66 60.47,9.36 61.43,9.36 63.77,11.7 63.77,27.55 62.38,28.93
VMAIN_PD on TOP: 37.45,13.84 37.45,14.86 37.88,15.29 37.88,16.31 37.93,16.36 38.77,16.36 38.82,16.31 38.82,14.97 38.66,14.81 38.66,13.84
VMAIN_PD on TOP: 28.97,24.75 27.72,24.75 26.97,24 26.97,22.96 27.06,22.87 27.59,22.87 28.3,22.17 29.64,22.17 29.71,22.23 29.71,23.07 29,23.79 29,24.72
VMAIN_PD on BOTTOM: 37.88,14.95 38.82,14.95 38.82,17.36 38.13,17.36 38.13,16.43 37.88,16.18
VMAIN_PD on L04_PWR1: 26.39,24.62 25.82,24.04 25.82,21.42 26.74,20.49 26.97,20.49 28.08,19.38 28.08,17.79 28.52,17.35 33.07,17.35 33.45,17.73 34.65,17.73 35.22,17.16 35.22,14.86 35.58,14.5 44.13,14.5 44.75,15.12 44.75,21.02 43.57,22.21 33.4,22.21 33.39,22.21 31.96,22.21 29.55,24.62
VPP_1V8 on TOP: 60.6,69.59 61.02,70.01 61.02,74.4 61.78,74.4 61.78,65.15 61.27,64.64 61.27,63.71 61.08,63.52 60.36,63.52 60.17,63.71 60.17,65.55 60.6,65.98
VPP_1V8 on BOTTOM: 71.03,76.35 71.03,75.87 70.65,75.49 69.99,75.49 69.86,75.36 69.86,75.03 69.69,74.87 69.69,73.5 69.56,73.37 66.13,73.37 65.72,73.78 65.72,74.88 66.18,75.34 68.82,75.34 69.96,76.48 70.9,76.48
VPP_SUPPLY on TOP: 61.66,60.05 61.66,64.51 61.9,64.75 62.66,64.75 62.77,64.65 62.77,62.01 62.31,61.56 62.31,60.07 62.3,60.05
XDS_SHIELD on TOP: 135.94,57 130.52,57 130.11,56.6 130.11,55.47 130.46,55.12 131.94,55.12 132.18,55.37 132.86,55.37 133.22,55.02 133.22,49.57 132.92,49.28 132.1,49.28 132.04,49.34 130.69,49.34 130.25,48.91 130.25,48.19 130.71,47.73 135.94,47.73
XDS_SHIELD on BOTTOM: 132.16,43.59 132.15,43.61 132.15,46.9 132.13,46.92 132.13,47.73 130.71,47.73 130.25,48.19 130.25,48.91 130.69,49.34 132.04,49.34 132.1,49.28 132.92,49.28 133.22,49.57 133.22,55.02 132.86,55.37 132.18,55.37 131.94,55.12 130.46,55.12 130.11,55.47 130.11,56.6 130.52,57 135.98,57 135.98,44.27 135.3,43.59
XDS_USB_VBUS on TOP: 132,51.22 130.58,51.22 129.84,50.47 128.26,50.47 128.1,50.63 128.1,51.65 127.98,51.77 127.45,51.77 127.18,52.04 127.18,54.35 130.54,57.71 133.74,57.71 135.93,59.9 135.93,66.05 135.65,66.32 134.78,66.32 134.52,66.06 134.52,65.15 134,64.63 126.98,64.63 126.35,65.26 119.56,65.26 119.56,64.59 119.64,64.5 121.62,64.5 121.84,64.27 123.46,64.27 124.21,63.52 124.21,61.01 123.59,61.01 123.1,60.52 120.25,60.52 120.11,60.37 120.11,50.03 120.46,49.68 127.8,49.68 127.81,49.68 130.3,49.68 131.06,50.44 131.83,50.44 132,50.61
N22682556 on BOTTOM (solid shape): 46.77,33.27 46.8,33.2 46.77,33.14 46.05,32.58 45.2,33.2 46.05,33.83
N24605606 on TOP (solid shape): 82.26,176.29 81.52,175.17 81.45,175.13 81.37,175.16 80.51,176.29 81.38,176.98
N24605846 on TOP: 81.09,157.32 81.09,153.96 82.42,153.96 82.42,155.77 81.56,156.63 81.56,158.35 81.1,158.35 81.1,157.32
N24847884 on BOTTOM (solid shape): 101.49,179.54 101.53,179.46 101.49,179.38 100.45,178.58 99.75,179.46 100.45,180.34
N24847886 on BOTTOM (solid shape): 109.79,179.48 109.89,178.39 108.65,178.23 108.57,178.26 108.54,178.34 108.71,179.57
N24848041 on TOP (solid shape): 111.05,176.96 110.35,176.08 109.29,176.9 109.25,176.97 109.29,177.05 110.35,177.84
N24848043 on TOP (solid shape): 99.79,175.8 99.76,175.72 99.68,175.69 98.38,175.86 98.51,176.98 99.62,177.1
N24851312 on BOTTOM (solid shape): 118.89,179.54 118.93,179.46 118.89,179.38 117.84,178.58 117.15,179.46 117.84,180.34
N24851456 on TOP (solid shape): 128.45,176.96 127.75,176.08 126.65,176.92 126.62,177 126.66,177.08 127.75,177.84
N24851458 on TOP (solid shape): 117.18,175.81 117.15,175.73 117.07,175.7 115.79,175.87 115.91,176.98 117.01,177.1
N25809420 on TOP: 94.59,42.98 94.59,38.69 92.75,38.69 92.75,42.98
N25809420 on TOP: 81.27,42.98 81.27,38.69 82.87,38.69 82.87,42.98
N25809420 on BOTTOM: 93.11,41.26 96.09,41.26 96.09,38.64 93.21,38.64 93.21,40.46 92.94,40.73 92.94,41.08
N25809420 on L05_SIG02: 81.58,42.22 82.96,40.84 82.96,38.94 82.68,38.66 80.89,38.66 79.47,40.08 79.47,46.85 81.53,48.91 92.41,48.91 95.02,46.3 95.02,38.9 94.78,38.65 93.04,38.65 92.63,39.05 92.63,44.78 90.8,46.62 82.46,46.62 81.58,45.73
N25815350 on TOP: 127.31,43.07 127.31,38.69 125.18,38.69 125.18,43.07
N25815350 on TOP: 113.69,43.2 113.69,38.69 115.3,38.69 115.3,43.2
N25815350 on BOTTOM: 112.88,41.26 114.96,41.26 115.1,41.13 115.1,40.29 114.72,39.91 114.72,38.71 114.59,38.58 113.03,38.58 112.8,38.81 112.8,39.5 112.65,39.65 112.65,41.03
N25815350 on L05_SIG02: 126.76,41.33 127.23,40.86 127.23,32.68 125.64,31.09 116.23,31.09 113.62,33.7 113.62,41.1 113.87,41.34 115.61,41.34 116.01,40.94 116.01,35.21 117.84,33.38 123.62,33.38 125.18,34.94 125.18,41.12 125.39,41.33
N26038205 on BOTTOM: 33.66,23.1 28.36,23.1 27.91,22.65 27.91,13.26 34.45,13.26 34.45,19.91 34.42,19.89 34.42,22.34
N27118438 on TOP: 44.01,81.47 44.01,80.86 44.19,80.68 44.19,79.79 44.11,79.71 44.11,78.77 43.95,78.61 42.68,78.61 42.22,79.06 42.22,81.59 43.89,81.59
N27162147 on BOTTOM: 53.1,14.24 53.1,15.53 53.27,15.7 55.53,15.7 55.53,18.23 52.54,18.23 52.51,18.21 52.51,14.24
N27162183 on TOP: 51.01,15.7 51.01,13.92 56.05,13.92 56.05,15.7
N27162183 on BOTTOM: 49.84,15.4 49.84,16.44 52.09,16.44 52.21,16.32 52.21,14 50.96,14 50.96,14.46 50.02,15.4
N27162183 on L04_PWR1: 56.85,22.01 52.39,22.01 51.91,21.54 51.91,17.57 50.87,16.53 50.87,13.44 51.17,13.14 58.69,13.14 58.82,13.27 58.82,18.15 58.16,18.82 57.74,18.82 57.18,19.37 57.18,21.68
N27162293 on BOTTOM: 49.53,15.28 49.53,16.36 46.43,16.36 46.43,15.37 46.53,15.28
N27175987 on TOP: 117.1,145.4 117.1,144.01 116.8,143.71 116.8,143 116.97,142.83 119.37,142.83 119.5,142.95 119.5,143.54 119.46,143.58 118.23,143.58 117.89,143.92 117.89,145.36 117.83,145.42 117.12,145.42
N27224561 on TOP: 69.43,161.37 69.43,162.79 69.05,162.79 69.05,163.05 68.42,163.05 68.42,165.8 69.96,165.8 69.96,161.35 69.44,161.35 69.44,161.37
N27225078 on TOP (solid shape): 65.11,176.29 64.38,175.17 64.3,175.13 64.22,175.16 63.36,176.29 64.23,176.98

Small or netless copper shapes (teardrops, artwork), in the pictures only: 2021 on TOP, 1703 on BOTTOM, 953 on L03_SIG01, 5 on L04_PWR1, 44 on L05_SIG02, 10 on L06_PWR2, 23 on L07_GND02

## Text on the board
Ref Des/Assembly Bottom: PROC180E1 ASSEMBLY BOTTOM
Ref Des/Silkscreen Bottom: uSD | B | FOR EVALUATION ONLY; | NOT FCC APPROVED FOR RESALE | ASSY#
User.Comments: CR_INI_5 | CR_1_24 | CR_1_21 | CR_11_1 | CR_UQFN16_TMUX1574_70X100_0-6_TOP_1 | CR_UQFN16_TMUX1574_70X100_0-6_TOP_2 | CR_INA_BGA_6 | CR_UNNAMED_1 | CR_ETH_114E1_1 | CR_3_2 | CR_1_9 | CR_UNNAMED_2 | CR_CAP_2 | BOARD NAME: | AM62D EVM  BOARD | REV: E1 | DATE: 29/04/24 | DESCRIPTION: | SHEET | OF | 15 | PROC180E1 | SCALE: 1 | TEXAS INSTRUMENTS
Ref Des/Assembly Top: PROC180E1 ASSEMBLY TOP
Ref Des/Silkscreen Top: FTDI_LED | 5V0_TYPEA | VDDR_CORE | MCU_RESETz | VDD_CANUART | VBUS_TYPEC2 | PORz_OUT | RESETSTATz | MCU_PORz | PMIC_PGOOD | PMIC_LPM_SEL | VBUS_TYPEC1 | 3V3_SYS | MCU_WARM_RST | VPP_1V8 | OSPI_FLASH | VBAT_IN | A | DGND | INT | RST | PMIC_CORE_CONFIG | BMODE 8-15 | BMODE 0-7 | UART | OPT_IN | VDD_MMC1_SD | VDDSHV_SDIO | VMAIN | 3V3_MAIN | MCAN_HDR | FTDI | DIR | PD_PGM | EXP_LED | 5V0 | MCU_RESETSTATz | DIT | PORz | DVDD_1V8 | LINE_IN_2 | LINE_IN_1 | ETH0_CONN | LINE_OUT_1 | JTAG_CTI | SOC_LED | LINE_OUT_2 | ETH1_CONN | JTAG | FT4232_VBUS | AEC1 | MCU_MCAN_HDR | CPLD2_JTAG | TYPE-C | PWR | DRP | VDD_LPDDR4 | TYPE-A CONN | LPDDR4 | VDD_CORE | CPLD1_JTAG | eMMC | 3V3_XDS | VDD_2V5 | 110 | XDS | AEC2 | XDS_USB_VBUS | AM62D EVM | PROC180E1 | OPN# | AUDIO-AM62D-EVM | SL#
